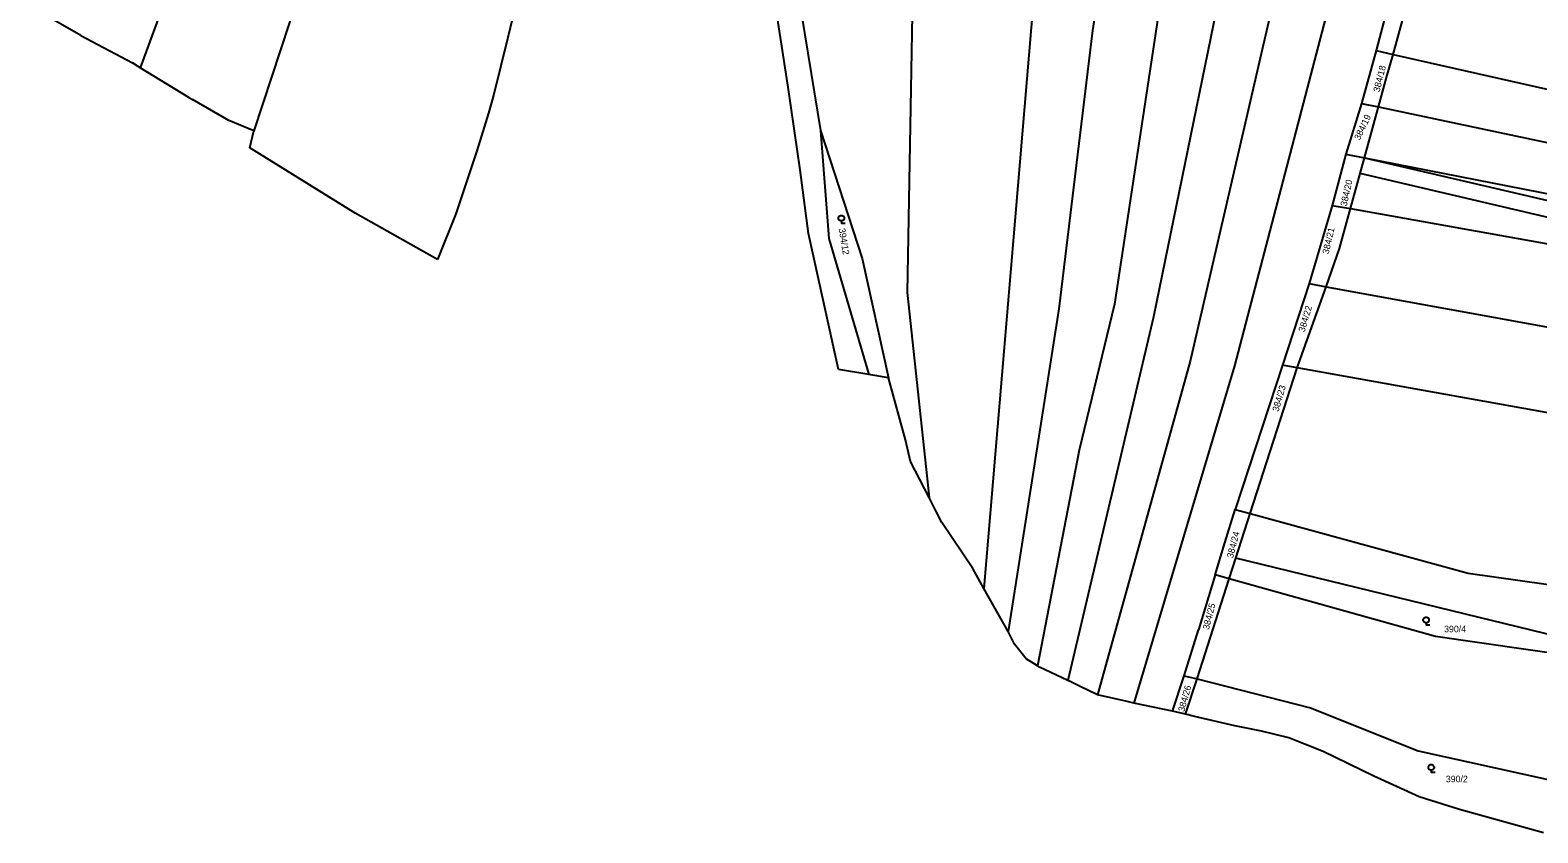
# Model space of a CAD drawing. Extents: x -580630 to -576196, y -1189024 to -1183567.
# Drawn here: x -580515.8 to -580125.3, y -1186717.6 to -1186509.6 of the extents above; entities that cross this region are included whole.
import ezdxf

# ---------------------------------------------------------------- set-up
doc = ezdxf.new("R2010")
doc.units = 0
for name, color, linetype in [('Vrstva 1', 7, 'Continuous'), ('Vrstva 13', 7, 'Continuous'), ('Vrstva 18', 7, 'Continuous'), ('Vrstva 25', 7, 'Continuous'), ('Vrstva 6', 7, 'Continuous')]:
    doc.layers.add(name, color=color, linetype=linetype)

msp = doc.modelspace()

# ---------------------------------------------------------------- linework, layer by layer
at = {"layer": 'Vrstva 1'}
for p, q in [((-580157.26, -1186477.54), (-580167.22, -1186514.9)), ((-580162.83, -1186515.9), (-580152.43, -1186478.62)), ((-580167.22, -1186514.9), (-580170.95, -1186528.59)), ((-580164.49, -1186521.86), (-580162.83, -1186515.9)), ((-580166.59, -1186529.51), (-580164.49, -1186521.86)), ((-580170.95, -1186528.59), (-580175.04, -1186541.76)), ((-580170.21, -1186542.71), (-580166.59, -1186529.51)), ((-580175.04, -1186541.76), (-580178.6, -1186555.01)), ((-580171.32, -1186546.75), (-580170.21, -1186542.71)), ((-580170.21, -1186542.71), (-579986.59, -1186585.43)), ((-580173.82, -1186555.87), (-580171.32, -1186546.75)), ((-579911.77, -1186607.7), (-580171.32, -1186546.75)), ((-580178.6, -1186555.01), (-580184.56, -1186575.28)), ((-580176.65, -1186566.22), (-580173.82, -1186555.87)), ((-580180.16, -1186576.08), (-580176.65, -1186566.22)), ((-580184.56, -1186575.28), (-580191.46, -1186596.4)), ((-580187.65, -1186597.09), (-580180.16, -1186576.08)), ((-580191.46, -1186596.4), (-580203.68, -1186633.81)), ((-580199.81, -1186634.87), (-580187.65, -1186597.09)), ((-580206.35, -1186642.43), (-580203.68, -1186633.81)), ((-580203.52, -1186646.39), (-580199.81, -1186634.87)), ((-580208.92, -1186650.71), (-580206.35, -1186642.43)), ((-580205.24, -1186651.74), (-580203.52, -1186646.39)), ((-580075.02, -1186677.84), (-580203.52, -1186646.39)), ((-580213.59, -1186677.7), (-580205.24, -1186651.74)), ((-580208.92, -1186650.71), (-580213.17, -1186664.97)), ((-580216.91, -1186676.85), (-580213.17, -1186664.97)), ((-580219.96, -1186686.05), (-580216.91, -1186676.85)), ((-580216.54, -1186686.86), (-580213.59, -1186677.7))]:
    msp.add_line(p, q, dxfattribs=at)
at = {"layer": 'Vrstva 13'}
for p, q in [((-580389.18, -1186499.4), (-580392.12, -1186511.86)), ((-580502.65, -1186511.03), (-580515.77, -1186503.53)), ((-580319.48, -1186524.37), (-580322.21, -1186506.5)), ((-580502.65, -1186511.03), (-580489.29, -1186518.13)), ((-580392.12, -1186511.86), (-580395.71, -1186526.17)), ((-580487.25, -1186519.37), (-580489.29, -1186518.13)), ((-580474.65, -1186527.04), (-580487.25, -1186519.37)), ((-580316.36, -1186545.8), (-580319.48, -1186524.37)), ((-580474.65, -1186527.04), (-580473.75, -1186527.59)), ((-580464.28, -1186532.99), (-580473.75, -1186527.59)), ((-580395.71, -1186526.17), (-580397.07, -1186531.14)), ((-580397.07, -1186531.14), (-580400.13, -1186540.9)), ((-580457.86, -1186535.69), (-580464.28, -1186532.99)), ((-580458.87, -1186540.08), (-580457.86, -1186535.69)), ((-580431.57, -1186557.07), (-580458.87, -1186540.08)), ((-580400.13, -1186540.9), (-580405.55, -1186557.24)), ((-580314.21, -1186562.33), (-580316.36, -1186545.8)), ((-580410.29, -1186569.05), (-580431.57, -1186557.07)), ((-580405.55, -1186557.24), (-580410.29, -1186569.05)), ((-580306.41, -1186597.57), (-580314.21, -1186562.33)), ((-580298.6, -1186598.86), (-580306.41, -1186597.57)), ((-580293.52, -1186599.7), (-580298.6, -1186598.86)), ((-580289.04, -1186615.79), (-580293.52, -1186599.7)), ((-580287.8, -1186621.37), (-580289.04, -1186615.79)), ((-580282.92, -1186630.68), (-580287.8, -1186621.37)), ((-580281.3, -1186633.98), (-580282.92, -1186630.68)), ((-580279.71, -1186637.21), (-580281.3, -1186633.98)), ((-580271.66, -1186649.06), (-580279.71, -1186637.21)), ((-580268.78, -1186654.23), (-580271.66, -1186649.06)), ((-580262.53, -1186665.42), (-580268.78, -1186654.23)), ((-580260.87, -1186668.73), (-580262.53, -1186665.42)), ((-580257.87, -1186672.46), (-580260.87, -1186668.73)), ((-580254.88, -1186674.31), (-580257.87, -1186672.46)), ((-580254.34, -1186674.64), (-580254.88, -1186674.31)), ((-580247.08, -1186678.11), (-580254.34, -1186674.64)), ((-580246.48, -1186678.4), (-580247.08, -1186678.11)), ((-580243.83, -1186679.67), (-580246.48, -1186678.4)), ((-580239.34, -1186681.82), (-580243.83, -1186679.67)), ((-580231.67, -1186683.57), (-580239.34, -1186681.82)), ((-580229.93, -1186683.94), (-580231.67, -1186683.57)), ((-580219.96, -1186686.05), (-580229.93, -1186683.94)), ((-580216.54, -1186686.86), (-580219.96, -1186686.05)), ((-580214.25, -1186687.4), (-580216.54, -1186686.86)), ((-580203.76, -1186689.88), (-580214.25, -1186687.4)), ((-580196.91, -1186691.22), (-580203.76, -1186689.88)), ((-580189.77, -1186692.97), (-580196.91, -1186691.22)), ((-580185.96, -1186694.49), (-580189.77, -1186692.97)), ((-580180.96, -1186696.49), (-580185.96, -1186694.49)), ((-580167.79, -1186702.91), (-580180.96, -1186696.49)), ((-580156.04, -1186708.27), (-580167.79, -1186702.91)), ((-580145.58, -1186711.48), (-580156.04, -1186708.27)), ((-580123.9, -1186717.57), (-580145.58, -1186711.48))]:
    msp.add_line(p, q, dxfattribs=at)
at = {"layer": 'Vrstva 25'}
for points in [[(-580305.7, -1186559.06), (-580305.89, -1186559.06), (-580306.23, -1186558.87), (-580306.42, -1186558.53), (-580306.42, -1186558.14), (-580306.23, -1186557.8), (-580305.89, -1186557.61), (-580305.5, -1186557.61), (-580305.16, -1186557.8), (-580304.97, -1186558.14), (-580304.97, -1186558.53), (-580305.16, -1186558.87), (-580305.5, -1186559.06), (-580305.69, -1186559.06), (-580305.69, -1186559.59), (-580304.69, -1186559.59)], [(-580154.27, -1186663.17), (-580154.46, -1186663.17), (-580154.8, -1186662.98), (-580154.99, -1186662.64), (-580154.99, -1186662.25), (-580154.8, -1186661.91), (-580154.46, -1186661.72), (-580154.07, -1186661.72), (-580153.73, -1186661.91), (-580153.54, -1186662.25), (-580153.54, -1186662.64), (-580153.73, -1186662.98), (-580154.07, -1186663.17), (-580154.26, -1186663.17), (-580154.26, -1186663.7), (-580153.26, -1186663.7)], [(-580152.94, -1186701.35), (-580153.13, -1186701.35), (-580153.47, -1186701.16), (-580153.66, -1186700.82), (-580153.66, -1186700.43), (-580153.47, -1186700.09), (-580153.13, -1186699.9), (-580152.74, -1186699.9), (-580152.4, -1186700.09), (-580152.21, -1186700.43), (-580152.21, -1186700.82), (-580152.4, -1186701.16), (-580152.74, -1186701.35), (-580152.93, -1186701.35), (-580152.93, -1186701.88), (-580151.93, -1186701.88)]]:
    msp.add_lwpolyline(points, dxfattribs=at)
at = {"layer": 'Vrstva 6'}
for p, q in [((-580438.68, -1186386.48), (-580487.25, -1186519.37)), ((-580189.95, -1186413.4), (-580224.9, -1186583.92)), ((-580173.77, -1186414.99), (-580215.37, -1186595.37)), ((-580226.8, -1186419.08), (-580240.63, -1186509.72)), ((-580425.45, -1186437.31), (-580457.86, -1186535.69)), ((-580220.55, -1186485.62), (-580234.94, -1186580.61)), ((-580175.01, -1186486.03), (-580203.89, -1186596.61)), ((-580317.45, -1186496.65), (-580311.13, -1186535.65)), ((-580287.22, -1186497.27), (-580288.69, -1186577.62)), ((-580255.93, -1186501.71), (-580268.78, -1186654.23)), ((-580240.63, -1186509.72), (-580249.36, -1186581.85)), ((-580167.22, -1186514.9), (-580162.83, -1186515.9)), ((-580162.83, -1186515.9), (-580029.98, -1186546.03)), ((-580170.95, -1186528.59), (-580166.59, -1186529.51)), ((-580166.59, -1186529.51), (-580043.49, -1186555.63)), ((-580311.13, -1186535.65), (-580300.3, -1186568.82)), ((-580311.13, -1186535.65), (-580308.91, -1186563.58)), ((-580175.04, -1186541.76), (-580170.21, -1186542.71)), ((-580170.21, -1186542.71), (-580063.58, -1186563.64)), ((-580178.6, -1186555.01), (-580173.82, -1186555.87)), ((-580173.82, -1186555.87), (-580075.49, -1186573.46)), ((-580308.91, -1186563.58), (-580298.6, -1186598.86)), ((-580300.3, -1186568.82), (-580293.52, -1186599.7)), ((-580184.56, -1186575.28), (-580180.16, -1186576.08)), ((-580288.69, -1186577.62), (-580282.92, -1186630.68)), ((-580180.16, -1186576.08), (-580080.02, -1186594.32)), ((-580249.36, -1186581.85), (-580262.53, -1186665.42)), ((-580234.94, -1186580.61), (-580244.07, -1186618.41)), ((-580224.9, -1186583.92), (-580247.08, -1186678.11)), ((-580215.37, -1186595.37), (-580239.34, -1186681.82)), ((-580203.89, -1186596.61), (-580229.93, -1186683.94)), ((-580187.65, -1186597.09), (-580191.46, -1186596.4)), ((-580069.99, -1186618.29), (-580187.65, -1186597.09)), ((-580244.07, -1186618.41), (-580254.88, -1186674.31)), ((-580203.68, -1186633.81), (-580199.81, -1186634.87)), ((-580199.81, -1186634.87), (-580143.41, -1186650.27)), ((-580205.24, -1186651.74), (-580208.92, -1186650.71)), ((-580151.84, -1186666.71), (-580205.24, -1186651.74)), ((-580143.41, -1186650.27), (-580076.39, -1186659.69)), ((-580075.02, -1186677.84), (-580151.84, -1186666.71)), ((-580216.91, -1186676.85), (-580213.59, -1186677.7)), ((-580213.59, -1186677.7), (-580184.19, -1186685.22)), ((-580184.19, -1186685.22), (-580156.33, -1186696.34)), ((-580156.33, -1186696.34), (-580098.87, -1186708.96))]:
    msp.add_line(p, q, dxfattribs=at)

# ---------------------------------------------------------------- texts
at = {"layer": 'Vrstva 18'}
for s, rotation, p in [('384/18', 76.08879, (-580166.33, -1186525.774)), ('384/19', 64.62964, (-580171.456, -1186538.273)), ('384/20', 77.17741, (-580174.842, -1186555.358)), ('394/12', 279.48881, (-580306.399, -1186561.079)), ('384/21', 77.00553, (-580179.501, -1186567.75)), ('384/22', 73.51049, (-580185.744, -1186587.963)), ('384/23', 73.79696, (-580192.497, -1186608.572)), ('384/24', 75.51584, (-580204.278, -1186646.513)), ('384/25', 75.51584, (-580210.51, -1186665.058)), ('384/26', 74.6564, (-580216.89, -1186686.326))]:
    msp.add_text(s, height=1.7, rotation=rotation, dxfattribs=at).set_placement(p)
for s, p in [('390/4', (-580149.597, -1186665.6)), ('390/2', (-580149.141, -1186704.46))]:
    msp.add_text(s, height=1.7, dxfattribs=at).set_placement(p)

doc.saveas('drawing.dxf')
